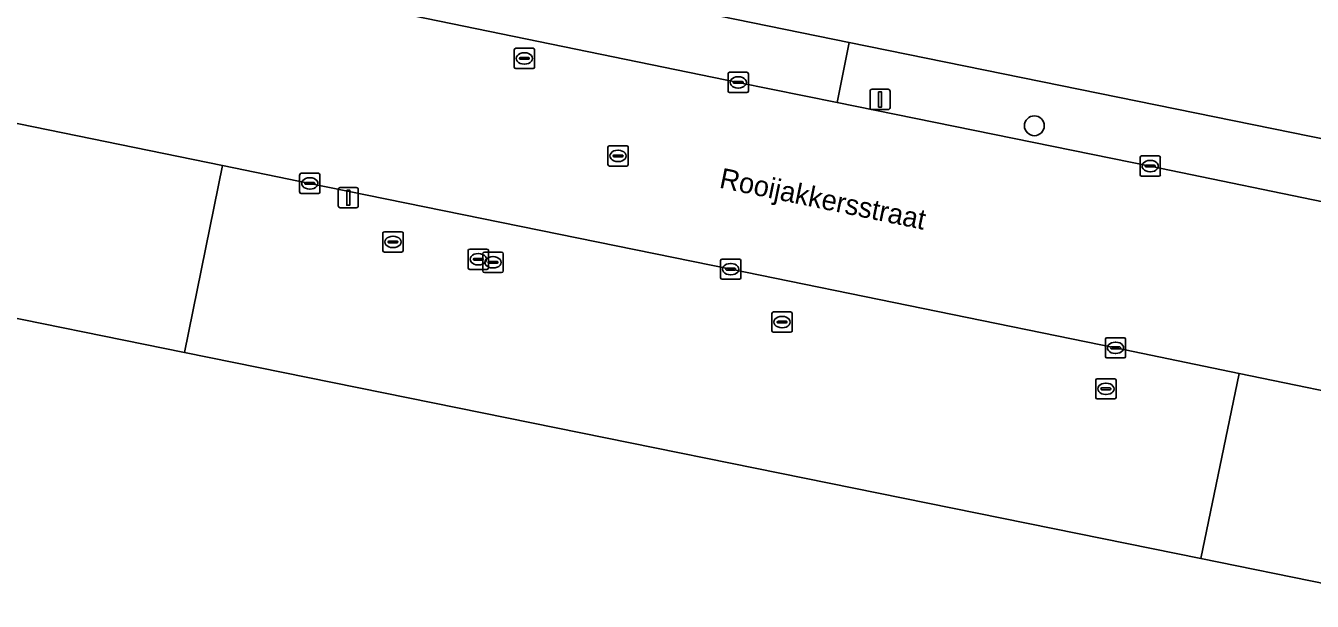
# Model space of a CAD drawing. Extents: x 157692 to 159674, y 381452 to 383291.
# Drawn here: x 158785 to 158848.6, y 382265.7 to 382294.1 of the extents above; entities that cross this region are included whole.
import ezdxf

# ---------------------------------------------------------------- set-up
doc = ezdxf.new("R2010")
doc.units = 0
for name, color, linetype in [('IMGEO_Boom', 7, 'Continuous'), ('IMGEO_Erf', 7, 'Continuous'), ('IMGEO_Kolk', 7, 'Continuous'), ('IMGEO_Lichtmast', 7, 'Continuous'), ('IMGEO_Openbare_ruimte_label', 7, 'Continuous'), ('IMGEO_Parkeervlak_gesloten', 7, 'Continuous'), ('IMGEO_Rijbaan_lokaal_open', 7, 'Continuous'), ('IMGEO_Rioolput', 7, 'Continuous'), ('IMGEO_Voetpad_open', 7, 'Continuous')]:
    doc.layers.add(name, color=color, linetype=linetype)

msp = doc.modelspace()

# ---------------------------------------------------------------- linework, layer by layer
at = {"layer": 'IMGEO_Boom'}
msp.add_circle((158834.835, 382289.174), 0.489, dxfattribs=at)
at = {"layer": 'IMGEO_Erf'}
for points in [[(158739.897, 382310.815), (158745.516, 382309.667), (158754.049, 382307.922), (158763.74, 382305.941), (158825.695, 382293.283), (158865.561, 382285.172), (158872.186, 382283.72), (158876.329, 382282.962), (158882.131, 382281.773), (158888.158, 382280.537), (158988.039, 382260.114), (159000, 382257.67), (159006.103, 382256.423), (159011.658, 382255.288), (159018.046, 382253.981), (159023.028, 382252.988), (159037.803, 382250), (159039.91, 382249.574), (159043.144, 382248.92), (159043.356, 382248.877), (159043.484, 382248.846), (159053.13, 382246.78), (159055.84, 382246.213), (159072.286, 382242.773)], [(158849.36, 382266.519), (158843.049, 382267.8), (158792.867, 382277.983), (158781.85, 382280.218), (158775.174, 382281.573), (158774.171, 382276.675), (158768.711, 382250), (158768.445, 382248.698), (158762.079, 382250), (158752.1, 382252.041), (158752.766, 382255.271), (158744.243, 382257.017), (158742.801, 382250), (158740.836, 382240.44), (158765.247, 382235.426), (158752.653, 382174.095)]]:
    msp.add_lwpolyline(points, dxfattribs=at)
at = {"layer": 'IMGEO_Kolk'}
for p, q in [((158819.787, 382291.817), (158820.639, 382291.817)), ((158819.712, 382290.891), (158819.712, 382291.743)), ((158819.971, 382291.311), (158819.971, 382291.323)), ((158820.409, 382291.274), (158820.011, 382291.274)), ((158820.014, 382291.36), (158820.412, 382291.36)), ((158820.2, 382291.597), (158820.225, 382291.597)), ((158820.455, 382291.323), (158820.455, 382291.311)), ((158820.713, 382291.743), (158820.713, 382290.891)), ((158820.639, 382290.817), (158819.787, 382290.817)), ((158820.223, 382291.037), (158820.198, 382291.037)), ((158840.053, 382286.756), (158840.053, 382287.608)), ((158840.128, 382287.682), (158840.98, 382287.682)), ((158840.541, 382287.462), (158840.566, 382287.462)), ((158841.054, 382287.608), (158841.054, 382286.756)), ((158798.559, 382285.899), (158798.559, 382286.751)), ((158798.634, 382286.825), (158799.486, 382286.825)), ((158799.56, 382286.751), (158799.56, 382285.899)), ((158840.312, 382287.176), (158840.312, 382287.188)), ((158840.75, 382287.139), (158840.352, 382287.139)), ((158840.355, 382287.225), (158840.753, 382287.225)), ((158840.564, 382286.902), (158840.539, 382286.902)), ((158840.796, 382287.188), (158840.796, 382287.176)), ((158798.818, 382286.319), (158798.818, 382286.331)), ((158799.256, 382286.282), (158798.858, 382286.282)), ((158798.861, 382286.368), (158799.259, 382286.368)), ((158799.047, 382286.605), (158799.072, 382286.605)), ((158799.302, 382286.331), (158799.302, 382286.319)), ((158840.98, 382286.682), (158840.128, 382286.682)), ((158799.486, 382285.825), (158798.634, 382285.825)), ((158799.07, 382286.045), (158799.045, 382286.045)), ((158802.667, 382283.01), (158802.667, 382283.862)), ((158802.742, 382283.936), (158803.594, 382283.936)), ((158803.155, 382283.716), (158803.18, 382283.716)), ((158803.668, 382283.862), (158803.668, 382283.01)), ((158803.594, 382282.936), (158802.742, 382282.936)), ((158802.926, 382283.43), (158802.926, 382283.442)), ((158803.364, 382283.393), (158802.966, 382283.393)), ((158802.969, 382283.479), (158803.367, 382283.479)), ((158803.178, 382283.156), (158803.153, 382283.156)), ((158803.41, 382283.442), (158803.41, 382283.43)), ((158819.343, 382281.664), (158819.343, 382282.516)), ((158819.418, 382282.59), (158820.27, 382282.59)), ((158819.831, 382282.37), (158819.856, 382282.37)), ((158820.344, 382282.516), (158820.344, 382281.664)), ((158819.602, 382282.084), (158819.602, 382282.096)), ((158820.04, 382282.047), (158819.642, 382282.047)), ((158819.645, 382282.133), (158820.043, 382282.133)), ((158819.854, 382281.81), (158819.829, 382281.81)), ((158820.086, 382282.096), (158820.086, 382282.084)), ((158820.27, 382281.59), (158819.418, 382281.59)), ((158821.875, 382279.051), (158821.875, 382279.903)), ((158821.95, 382279.977), (158822.802, 382279.977)), ((158822.363, 382279.757), (158822.388, 382279.757)), ((158822.876, 382279.903), (158822.876, 382279.051)), ((158822.134, 382279.471), (158822.134, 382279.483)), ((158822.572, 382279.434), (158822.174, 382279.434)), ((158822.177, 382279.52), (158822.575, 382279.52)), ((158822.386, 382279.197), (158822.361, 382279.197)), ((158822.618, 382279.483), (158822.618, 382279.471)), ((158822.802, 382278.977), (158821.95, 382278.977)), ((158838.341, 382277.779), (158838.341, 382278.631)), ((158838.416, 382278.705), (158839.268, 382278.705)), ((158838.829, 382278.485), (158838.854, 382278.485)), ((158839.342, 382278.631), (158839.342, 382277.779)), ((158838.6, 382278.199), (158838.6, 382278.211)), ((158839.038, 382278.162), (158838.64, 382278.162)), ((158838.643, 382278.248), (158839.041, 382278.248)), ((158838.852, 382277.925), (158838.827, 382277.925)), ((158839.084, 382278.211), (158839.084, 382278.199)), ((158839.268, 382277.705), (158838.416, 382277.705)), ((158837.866, 382275.754), (158837.866, 382276.606)), ((158837.941, 382276.68), (158838.793, 382276.68)), ((158838.867, 382276.606), (158838.867, 382275.754)), ((158838.125, 382276.174), (158838.125, 382276.186)), ((158838.563, 382276.137), (158838.165, 382276.137)), ((158838.168, 382276.223), (158838.566, 382276.223)), ((158838.377, 382275.9), (158838.352, 382275.9)), ((158838.354, 382276.46), (158838.379, 382276.46)), ((158838.609, 382276.186), (158838.609, 382276.174)), ((158838.793, 382275.68), (158837.941, 382275.68))]:
    msp.add_line(p, q, dxfattribs=at)
for points in [[(158819.787, 382291.817), (158820.639, 382291.817)], [(158819.712, 382290.891), (158819.712, 382291.743)], [(158820.713, 382291.743), (158820.713, 382290.891)], [(158820.639, 382290.817), (158819.787, 382290.817)], [(158840.053, 382286.756), (158840.053, 382287.608)], [(158840.128, 382287.682), (158840.98, 382287.682)], [(158841.054, 382287.608), (158841.054, 382286.756)], [(158798.559, 382285.899), (158798.559, 382286.751)], [(158798.634, 382286.825), (158799.486, 382286.825)], [(158799.56, 382286.751), (158799.56, 382285.899)], [(158840.98, 382286.682), (158840.128, 382286.682)], [(158799.486, 382285.825), (158798.634, 382285.825)], [(158802.667, 382283.01), (158802.667, 382283.862)], [(158802.742, 382283.936), (158803.594, 382283.936)], [(158803.668, 382283.862), (158803.668, 382283.01)], [(158803.594, 382282.936), (158802.742, 382282.936)], [(158819.343, 382281.664), (158819.343, 382282.516)], [(158819.418, 382282.59), (158820.27, 382282.59)], [(158820.344, 382282.516), (158820.344, 382281.664)], [(158820.27, 382281.59), (158819.418, 382281.59)], [(158821.875, 382279.051), (158821.875, 382279.903)], [(158821.95, 382279.977), (158822.802, 382279.977)], [(158822.876, 382279.903), (158822.876, 382279.051)], [(158822.802, 382278.977), (158821.95, 382278.977)], [(158838.341, 382277.779), (158838.341, 382278.631)], [(158838.416, 382278.705), (158839.268, 382278.705)], [(158839.342, 382278.631), (158839.342, 382277.779)], [(158839.268, 382277.705), (158838.416, 382277.705)], [(158837.866, 382275.754), (158837.866, 382276.606)], [(158837.941, 382276.68), (158838.793, 382276.68)], [(158838.867, 382276.606), (158838.867, 382275.754)], [(158838.793, 382275.68), (158837.941, 382275.68)]]:
    msp.add_lwpolyline(points, dxfattribs=at)
for centre, radius, start, end in [((158819.789, 382291.741), 0.0765, 91.55205, 178.44795), ((158819.789, 382291.741), 0.0765, 91.55205, 178.44795), ((158820.637, 382291.741), 0.0765, 1.55205, 88.44795), ((158820.637, 382291.741), 0.0765, 1.55205, 88.44795), ((158820.011, 382291.32), 0.0403, 85.87752, 175.75265), ((158820.008, 382291.31), 0.0366, 178.93798, 274.71019), ((158820.412, 382291.317), 0.043, 264.86636, 352.45326), ((158820.416, 382291.322), 0.0386, 1.73085, 96.63898), ((158819.789, 382290.893), 0.0765, 181.55205, 268.44795), ((158819.789, 382290.893), 0.0765, 181.55205, 268.44795), ((158820.637, 382290.893), 0.0765, 271.55205, 358.44795), ((158820.637, 382290.893), 0.0765, 271.55205, 358.44795), ((158840.13, 382287.606), 0.0765, 91.55205, 178.44795), ((158840.13, 382287.606), 0.0765, 91.55205, 178.44795), ((158840.978, 382287.606), 0.0765, 1.55205, 88.44795), ((158840.978, 382287.606), 0.0765, 1.55205, 88.44795), ((158798.636, 382286.749), 0.0765, 91.55205, 178.44795), ((158798.636, 382286.749), 0.0765, 91.55205, 178.44795), ((158799.484, 382286.749), 0.0765, 1.55205, 88.44795), ((158799.484, 382286.749), 0.0765, 1.55205, 88.44795), ((158840.13, 382286.758), 0.0765, 181.55205, 268.44795), ((158840.13, 382286.758), 0.0765, 181.55205, 268.44795), ((158840.352, 382287.185), 0.0403, 85.87752, 175.75265), ((158840.349, 382287.175), 0.0366, 178.93798, 274.71019), ((158840.753, 382287.182), 0.043, 264.86636, 352.45326), ((158840.757, 382287.187), 0.0386, 1.73085, 96.63898), ((158840.978, 382286.758), 0.0765, 271.55205, 358.44795), ((158840.978, 382286.758), 0.0765, 271.55205, 358.44795), ((158798.858, 382286.328), 0.0403, 85.87752, 175.75265), ((158798.855, 382286.318), 0.0366, 178.93798, 274.71019), ((158799.259, 382286.325), 0.043, 264.86636, 352.45326), ((158799.263, 382286.33), 0.0386, 1.73085, 96.63898), ((158798.636, 382285.901), 0.0765, 181.55205, 268.44795), ((158798.636, 382285.901), 0.0765, 181.55205, 268.44795), ((158799.484, 382285.901), 0.0765, 271.55205, 358.44795), ((158799.484, 382285.901), 0.0765, 271.55205, 358.44795), ((158802.744, 382283.86), 0.0765, 91.55205, 178.44795), ((158802.744, 382283.86), 0.0765, 91.55205, 178.44795), ((158803.592, 382283.86), 0.0765, 1.55205, 88.44795), ((158803.592, 382283.86), 0.0765, 1.55205, 88.44795), ((158802.744, 382283.012), 0.0765, 181.55205, 268.44795), ((158802.744, 382283.012), 0.0765, 181.55205, 268.44795), ((158802.966, 382283.439), 0.0403, 85.87752, 175.75265), ((158802.963, 382283.429), 0.0366, 178.93798, 274.71019), ((158803.367, 382283.436), 0.043, 264.86636, 352.45326), ((158803.371, 382283.441), 0.0386, 1.73085, 96.63898), ((158803.592, 382283.012), 0.0765, 271.55205, 358.44795), ((158803.592, 382283.012), 0.0765, 271.55205, 358.44795), ((158819.42, 382282.514), 0.0765, 91.55205, 178.44795), ((158819.42, 382282.514), 0.0765, 91.55205, 178.44795), ((158820.268, 382282.514), 0.0765, 1.55205, 88.44795), ((158820.268, 382282.514), 0.0765, 1.55205, 88.44795), ((158819.42, 382281.666), 0.0765, 181.55205, 268.44795), ((158819.42, 382281.666), 0.0765, 181.55205, 268.44795), ((158819.642, 382282.093), 0.0403, 85.87752, 175.75265), ((158819.639, 382282.083), 0.0366, 178.93798, 274.71019), ((158820.043, 382282.09), 0.043, 264.86636, 352.45326), ((158820.047, 382282.095), 0.0386, 1.73085, 96.63898), ((158820.268, 382281.666), 0.0765, 271.55205, 358.44795), ((158820.268, 382281.666), 0.0765, 271.55205, 358.44795), ((158821.952, 382279.901), 0.0765, 91.55205, 178.44795), ((158821.952, 382279.901), 0.0765, 91.55205, 178.44795), ((158822.8, 382279.901), 0.0765, 1.55205, 88.44795), ((158822.8, 382279.901), 0.0765, 1.55205, 88.44795), ((158822.174, 382279.48), 0.0403, 85.87752, 175.75265), ((158822.171, 382279.47), 0.0366, 178.93798, 274.71019), ((158822.575, 382279.477), 0.043, 264.86636, 352.45326), ((158822.579, 382279.482), 0.0386, 1.73085, 96.63898), ((158821.952, 382279.053), 0.0765, 181.55205, 268.44795), ((158821.952, 382279.053), 0.0765, 181.55205, 268.44795), ((158822.8, 382279.053), 0.0765, 271.55205, 358.44795), ((158822.8, 382279.053), 0.0765, 271.55205, 358.44795), ((158838.418, 382278.629), 0.0765, 91.55205, 178.44795), ((158838.418, 382278.629), 0.0765, 91.55205, 178.44795), ((158839.266, 382278.629), 0.0765, 1.55205, 88.44795), ((158839.266, 382278.629), 0.0765, 1.55205, 88.44795), ((158838.64, 382278.208), 0.0403, 85.87752, 175.75265), ((158838.637, 382278.198), 0.0366, 178.93798, 274.71019), ((158839.041, 382278.205), 0.043, 264.86636, 352.45326), ((158839.045, 382278.21), 0.0386, 1.73085, 96.63898), ((158838.418, 382277.781), 0.0765, 181.55205, 268.44795), ((158838.418, 382277.781), 0.0765, 181.55205, 268.44795), ((158839.266, 382277.781), 0.0765, 271.55205, 358.44795), ((158839.266, 382277.781), 0.0765, 271.55205, 358.44795), ((158837.943, 382276.604), 0.0765, 91.55205, 178.44795), ((158837.943, 382276.604), 0.0765, 91.55205, 178.44795), ((158838.791, 382276.604), 0.0765, 1.55205, 88.44795), ((158838.791, 382276.604), 0.0765, 1.55205, 88.44795), ((158838.165, 382276.183), 0.0403, 85.87752, 175.75265), ((158838.162, 382276.173), 0.0366, 178.93798, 274.71019), ((158838.566, 382276.18), 0.043, 264.86636, 352.45326), ((158838.57, 382276.185), 0.0386, 1.73085, 96.63898), ((158837.943, 382275.756), 0.0765, 181.55205, 268.44795), ((158837.943, 382275.756), 0.0765, 181.55205, 268.44795), ((158838.791, 382275.756), 0.0765, 271.55205, 358.44795), ((158838.791, 382275.756), 0.0765, 271.55205, 358.44795)]:
    msp.add_arc(centre, radius, start, end, dxfattribs=at)
for centre, major_axis, ratio, start_param, end_param in [((158820.199, 382291.317), (-0.387, 0.002), 0.722429, 4.712389, 7.853982), ((158820.224, 382291.317), (-0.39, 0.002), 0.717154, 1.570796, 4.712389), ((158840.54, 382287.182), (-0.387, 0.002), 0.722429, 4.712389, 7.853982), ((158840.565, 382287.182), (-0.39, 0.002), 0.717154, 1.570796, 4.712389), ((158799.046, 382286.325), (-0.387, 0.002), 0.722429, 4.712389, 7.853982), ((158799.071, 382286.325), (-0.39, 0.002), 0.717154, 1.570796, 4.712389), ((158803.154, 382283.436), (-0.387, 0.002), 0.722429, 4.712389, 7.853982), ((158803.179, 382283.436), (-0.39, 0.002), 0.717154, 1.570796, 4.712389), ((158819.83, 382282.09), (-0.387, 0.002), 0.722429, 4.712389, 7.853982), ((158819.855, 382282.09), (-0.39, 0.002), 0.717154, 1.570796, 4.712389), ((158822.362, 382279.477), (-0.387, 0.002), 0.722429, 4.712389, 7.853982), ((158822.387, 382279.477), (-0.39, 0.002), 0.717154, 1.570796, 4.712389), ((158838.828, 382278.205), (-0.387, 0.002), 0.722429, 4.712389, 7.853982), ((158838.853, 382278.205), (-0.39, 0.002), 0.717154, 1.570796, 4.712389), ((158838.353, 382276.18), (-0.387, 0.002), 0.722429, 4.712389, 7.853982), ((158838.378, 382276.18), (-0.39, 0.002), 0.717154, 1.570796, 4.712389)]:
    msp.add_ellipse(centre, major_axis=major_axis, ratio=ratio, start_param=start_param, end_param=end_param, dxfattribs=at)
at = {"layer": 'IMGEO_Lichtmast'}
for p, q in [((158826.723, 382290.074), (158826.723, 382290.874)), ((158826.723, 382290.874), (158826.723, 382290.074)), ((158826.823, 382290.974), (158827.613, 382290.974)), ((158827.613, 382290.974), (158826.823, 382290.974)), ((158827.713, 382290.874), (158827.713, 382290.074)), ((158827.713, 382290.074), (158827.713, 382290.874)), ((158827.613, 382289.974), (158826.823, 382289.974)), ((158826.823, 382289.974), (158827.613, 382289.974)), ((158800.565, 382286.124), (158801.355, 382286.124)), ((158801.355, 382286.124), (158800.565, 382286.124)), ((158800.465, 382285.224), (158800.465, 382286.024)), ((158800.465, 382286.024), (158800.465, 382285.224)), ((158801.455, 382286.024), (158801.455, 382285.224)), ((158801.455, 382285.224), (158801.455, 382286.024)), ((158801.355, 382285.124), (158800.565, 382285.124)), ((158800.565, 382285.124), (158801.355, 382285.124))]:
    msp.add_line(p, q, dxfattribs=at)
for points in [[(158827.143, 382290.849), (158827.293, 382290.849), (158827.293, 382290.099), (158827.143, 382290.099), (158827.143, 382290.849)], [(158800.885, 382285.999), (158801.035, 382285.999), (158801.035, 382285.249), (158800.885, 382285.249), (158800.885, 382285.999)]]:
    msp.add_lwpolyline(points, dxfattribs=at)
for centre, start, end in [((158826.823, 382290.874), 90, 180), ((158826.823, 382290.874), 90, 180), ((158827.613, 382290.874), 0, 90), ((158827.613, 382290.874), 360, 90), ((158826.823, 382290.074), 180, 270), ((158826.823, 382290.074), 180, 270), ((158827.613, 382290.074), 270, 0), ((158827.613, 382290.074), 270, 0), ((158800.565, 382286.024), 90, 180), ((158800.565, 382286.024), 90, 180), ((158801.355, 382286.024), 0, 90), ((158801.355, 382286.024), 360, 90), ((158800.565, 382285.224), 180, 270), ((158800.565, 382285.224), 180, 270), ((158801.355, 382285.224), 270, 0), ((158801.355, 382285.224), 270, 0)]:
    msp.add_arc(centre, 0.1, start, end, dxfattribs=at)
at = {"layer": 'IMGEO_Parkeervlak_gesloten'}
msp.add_lwpolyline([(158844.942, 382276.94), (158838.842, 382278.204), (158819.844, 382282.089), (158799.061, 382286.324), (158794.751, 382287.205), (158792.867, 382277.983), (158843.049, 382267.8)], close=True, dxfattribs=at)
at = {"layer": 'IMGEO_Rijbaan_lokaal_open'}
for points in [[(158585.369, 382330.295), (158606.304, 382326.032), (158627.099, 382321.705), (158645.918, 382317.846), (158664.706, 382313.983), (158683.357, 382310.127), (158703.229, 382305.989), (158720.558, 382302.454), (158740.076, 382298.433), (158761.28, 382294.05), (158776.976, 382290.837), (158783.229, 382289.567), (158794.751, 382287.205), (158799.061, 382286.324), (158819.844, 382282.089), (158838.842, 382278.204), (158844.942, 382276.94), (158852.145, 382275.448)], [(158859.681, 382283.22), (158840.554, 382287.183), (158825.094, 382290.327), (158820.213, 382291.319), (158800.497, 382295.362), (158780.293, 382299.514), (158763.168, 382302.997), (158761.821, 382303.271), (158753.419, 382304.996), (158744.89, 382306.754)]]:
    msp.add_lwpolyline(points, dxfattribs=at)
at = {"layer": 'IMGEO_Rioolput'}
for p, q in [((158809.155, 382292.073), (158809.155, 382292.925)), ((158809.23, 382292.999), (158810.082, 382292.999)), ((158809.414, 382292.493), (158809.414, 382292.505)), ((158809.852, 382292.456), (158809.454, 382292.456)), ((158809.457, 382292.542), (158809.855, 382292.542)), ((158809.643, 382292.779), (158809.668, 382292.779)), ((158809.898, 382292.505), (158809.898, 382292.493)), ((158810.156, 382292.925), (158810.156, 382292.073)), ((158810.082, 382291.999), (158809.23, 382291.999)), ((158809.666, 382292.219), (158809.641, 382292.219)), ((158813.781, 382287.259), (158813.781, 382288.111)), ((158813.856, 382288.185), (158814.708, 382288.185)), ((158814.782, 382288.111), (158814.782, 382287.259)), ((158814.04, 382287.679), (158814.04, 382287.691)), ((158814.478, 382287.642), (158814.08, 382287.642)), ((158814.083, 382287.728), (158814.481, 382287.728)), ((158814.292, 382287.405), (158814.267, 382287.405)), ((158814.269, 382287.965), (158814.294, 382287.965)), ((158814.524, 382287.691), (158814.524, 382287.679)), ((158814.708, 382287.185), (158813.856, 382287.185)), ((158806.88, 382282.156), (158806.88, 382283.008)), ((158806.955, 382283.082), (158807.807, 382283.082)), ((158807.679, 382282.929), (158808.531, 382282.929)), ((158807.881, 382283.008), (158807.881, 382282.156)), ((158807.139, 382282.576), (158807.139, 382282.588)), ((158807.577, 382282.539), (158807.179, 382282.539)), ((158807.182, 382282.625), (158807.58, 382282.625)), ((158807.391, 382282.302), (158807.366, 382282.302)), ((158807.368, 382282.862), (158807.393, 382282.862)), ((158807.604, 382282.003), (158807.604, 382282.855)), ((158807.623, 382282.588), (158807.623, 382282.576)), ((158807.863, 382282.423), (158807.863, 382282.435)), ((158808.301, 382282.386), (158807.903, 382282.386)), ((158807.906, 382282.472), (158808.304, 382282.472)), ((158808.092, 382282.709), (158808.117, 382282.709)), ((158808.347, 382282.435), (158808.347, 382282.423)), ((158808.605, 382282.855), (158808.605, 382282.003)), ((158807.807, 382282.082), (158806.955, 382282.082)), ((158808.531, 382281.929), (158807.679, 382281.929)), ((158808.115, 382282.149), (158808.09, 382282.149))]:
    msp.add_line(p, q, dxfattribs=at)
for points in [[(158809.155, 382292.073), (158809.155, 382292.925)], [(158809.23, 382292.999), (158810.082, 382292.999)], [(158810.156, 382292.925), (158810.156, 382292.073)], [(158810.082, 382291.999), (158809.23, 382291.999)], [(158813.781, 382287.259), (158813.781, 382288.111)], [(158813.856, 382288.185), (158814.708, 382288.185)], [(158814.782, 382288.111), (158814.782, 382287.259)], [(158814.708, 382287.185), (158813.856, 382287.185)], [(158806.88, 382282.156), (158806.88, 382283.008)], [(158806.955, 382283.082), (158807.807, 382283.082)], [(158807.679, 382282.929), (158808.531, 382282.929)], [(158807.881, 382283.008), (158807.881, 382282.156)], [(158807.604, 382282.003), (158807.604, 382282.855)], [(158808.605, 382282.855), (158808.605, 382282.003)], [(158807.807, 382282.082), (158806.955, 382282.082)], [(158808.531, 382281.929), (158807.679, 382281.929)]]:
    msp.add_lwpolyline(points, dxfattribs=at)
for centre, radius, start, end in [((158809.232, 382292.923), 0.0765, 91.55205, 178.44795), ((158809.232, 382292.923), 0.0765, 91.55205, 178.44795), ((158809.454, 382292.502), 0.0403, 85.87752, 175.75265), ((158809.451, 382292.492), 0.0366, 178.93798, 274.71019), ((158809.855, 382292.499), 0.043, 264.86636, 352.45326), ((158809.859, 382292.504), 0.0386, 1.73085, 96.63898), ((158810.08, 382292.923), 0.0765, 1.55205, 88.44795), ((158810.08, 382292.923), 0.0765, 1.55205, 88.44795), ((158809.232, 382292.075), 0.0765, 181.55205, 268.44795), ((158809.232, 382292.075), 0.0765, 181.55205, 268.44795), ((158810.08, 382292.075), 0.0765, 271.55205, 358.44795), ((158810.08, 382292.075), 0.0765, 271.55205, 358.44795), ((158813.858, 382288.109), 0.0765, 91.55205, 178.44795), ((158813.858, 382288.109), 0.0765, 91.55205, 178.44795), ((158814.706, 382288.109), 0.0765, 1.55205, 88.44795), ((158814.706, 382288.109), 0.0765, 1.55205, 88.44795), ((158814.08, 382287.688), 0.0403, 85.87752, 175.75265), ((158814.077, 382287.678), 0.0366, 178.93798, 274.71019), ((158814.481, 382287.685), 0.043, 264.86636, 352.45326), ((158814.485, 382287.69), 0.0386, 1.73085, 96.63898), ((158813.858, 382287.261), 0.0765, 181.55205, 268.44795), ((158813.858, 382287.261), 0.0765, 181.55205, 268.44795), ((158814.706, 382287.261), 0.0765, 271.55205, 358.44795), ((158814.706, 382287.261), 0.0765, 271.55205, 358.44795), ((158806.957, 382283.006), 0.0765, 91.55205, 178.44795), ((158806.957, 382283.006), 0.0765, 91.55205, 178.44795), ((158807.681, 382282.853), 0.0765, 91.55205, 178.44795), ((158807.681, 382282.853), 0.0765, 91.55205, 178.44795), ((158807.805, 382283.006), 0.0765, 1.55205, 88.44795), ((158807.805, 382283.006), 0.0765, 1.55205, 88.44795), ((158808.529, 382282.853), 0.0765, 1.55205, 88.44795), ((158808.529, 382282.853), 0.0765, 1.55205, 88.44795), ((158807.179, 382282.585), 0.0403, 85.87752, 175.75265), ((158807.176, 382282.575), 0.0366, 178.93798, 274.71019), ((158807.58, 382282.582), 0.043, 264.86636, 352.45326), ((158807.584, 382282.587), 0.0386, 1.73085, 96.63898), ((158807.903, 382282.432), 0.0403, 85.87752, 175.75265), ((158807.9, 382282.422), 0.0366, 178.93798, 274.71019), ((158808.304, 382282.429), 0.043, 264.86636, 352.45326), ((158808.308, 382282.434), 0.0386, 1.73085, 96.63898), ((158806.957, 382282.158), 0.0765, 181.55205, 268.44795), ((158806.957, 382282.158), 0.0765, 181.55205, 268.44795), ((158807.681, 382282.005), 0.0765, 181.55205, 268.44795), ((158807.681, 382282.005), 0.0765, 181.55205, 268.44795), ((158807.805, 382282.158), 0.0765, 271.55205, 358.44795), ((158807.805, 382282.158), 0.0765, 271.55205, 358.44795), ((158808.529, 382282.005), 0.0765, 271.55205, 358.44795), ((158808.529, 382282.005), 0.0765, 271.55205, 358.44795)]:
    msp.add_arc(centre, radius, start, end, dxfattribs=at)
for centre, major_axis, ratio, start_param, end_param in [((158809.642, 382292.499), (-0.387, 0.002), 0.722429, 4.712389, 7.853982), ((158809.667, 382292.499), (-0.39, 0.002), 0.717154, 1.570796, 4.712389), ((158814.268, 382287.685), (-0.387, 0.002), 0.722429, 4.712389, 7.853982), ((158814.293, 382287.685), (-0.39, 0.002), 0.717154, 1.570796, 4.712389), ((158807.367, 382282.582), (-0.387, 0.002), 0.722429, 4.712389, 7.853982), ((158807.392, 382282.582), (-0.39, 0.002), 0.717154, 1.570796, 4.712389), ((158808.091, 382282.429), (-0.387, 0.002), 0.722429, 4.712389, 7.853982), ((158808.116, 382282.429), (-0.39, 0.002), 0.717154, 1.570796, 4.712389)]:
    msp.add_ellipse(centre, major_axis=major_axis, ratio=ratio, start_param=start_param, end_param=end_param, dxfattribs=at)
at = {"layer": 'IMGEO_Voetpad_open'}
for points in [[(158825.695, 382293.283), (158763.74, 382305.941), (158763.168, 382302.997), (158780.293, 382299.514), (158800.497, 382295.362), (158820.213, 382291.319), (158825.094, 382290.327)], [(158864.974, 382282.191), (158865.561, 382285.172), (158825.695, 382293.283), (158825.094, 382290.327), (158840.554, 382287.183), (158859.681, 382283.22)]]:
    msp.add_lwpolyline(points, close=True, dxfattribs=at)
for points in [[(158783.638, 382288.95), (158783.509, 382288.325), (158781.85, 382280.218), (158792.867, 382277.983), (158794.751, 382287.205), (158783.229, 382289.567)], [(158851.612, 382272.861), (158852.145, 382275.448), (158844.942, 382276.94), (158843.049, 382267.8), (158849.36, 382266.519), (158849.63, 382267.906), (158850.654, 382272.966)]]:
    msp.add_lwpolyline(points, dxfattribs=at)

# ---------------------------------------------------------------- texts
at = {"layer": 'IMGEO_Openbare_ruimte_label'}
msp.add_text('Rooijakkersstraat', height=1, rotation=348.3416, dxfattribs=at).set_placement((158819.236, 382286.123))

doc.saveas('drawing.dxf')
